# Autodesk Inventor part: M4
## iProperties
IsCustomPart: 0
Created: 2009-02
Part Number: M4
Material: Steel, Mild
Description: 6각머리 태핑 나사
Document SubType Name: Modeling
Standard: KS B 1003
Designer: SeoGD™ [www.esajin.kr]
Standards Organization: KS
Language: ko-KR
Size Designation: M 4 x 10
Categories: <MemberInstance><Categories><Category DisplayName="조임쇠" InternalName="e4da775c-781d-43d5-af7c-5136215cf5a6" Mnemonic="FSTN"><Category DisplayName="볼트" InternalN
Density: 1 g/cm^3
Author: SeoGD™ [www.esajin.kr]
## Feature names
1. Fillet2
